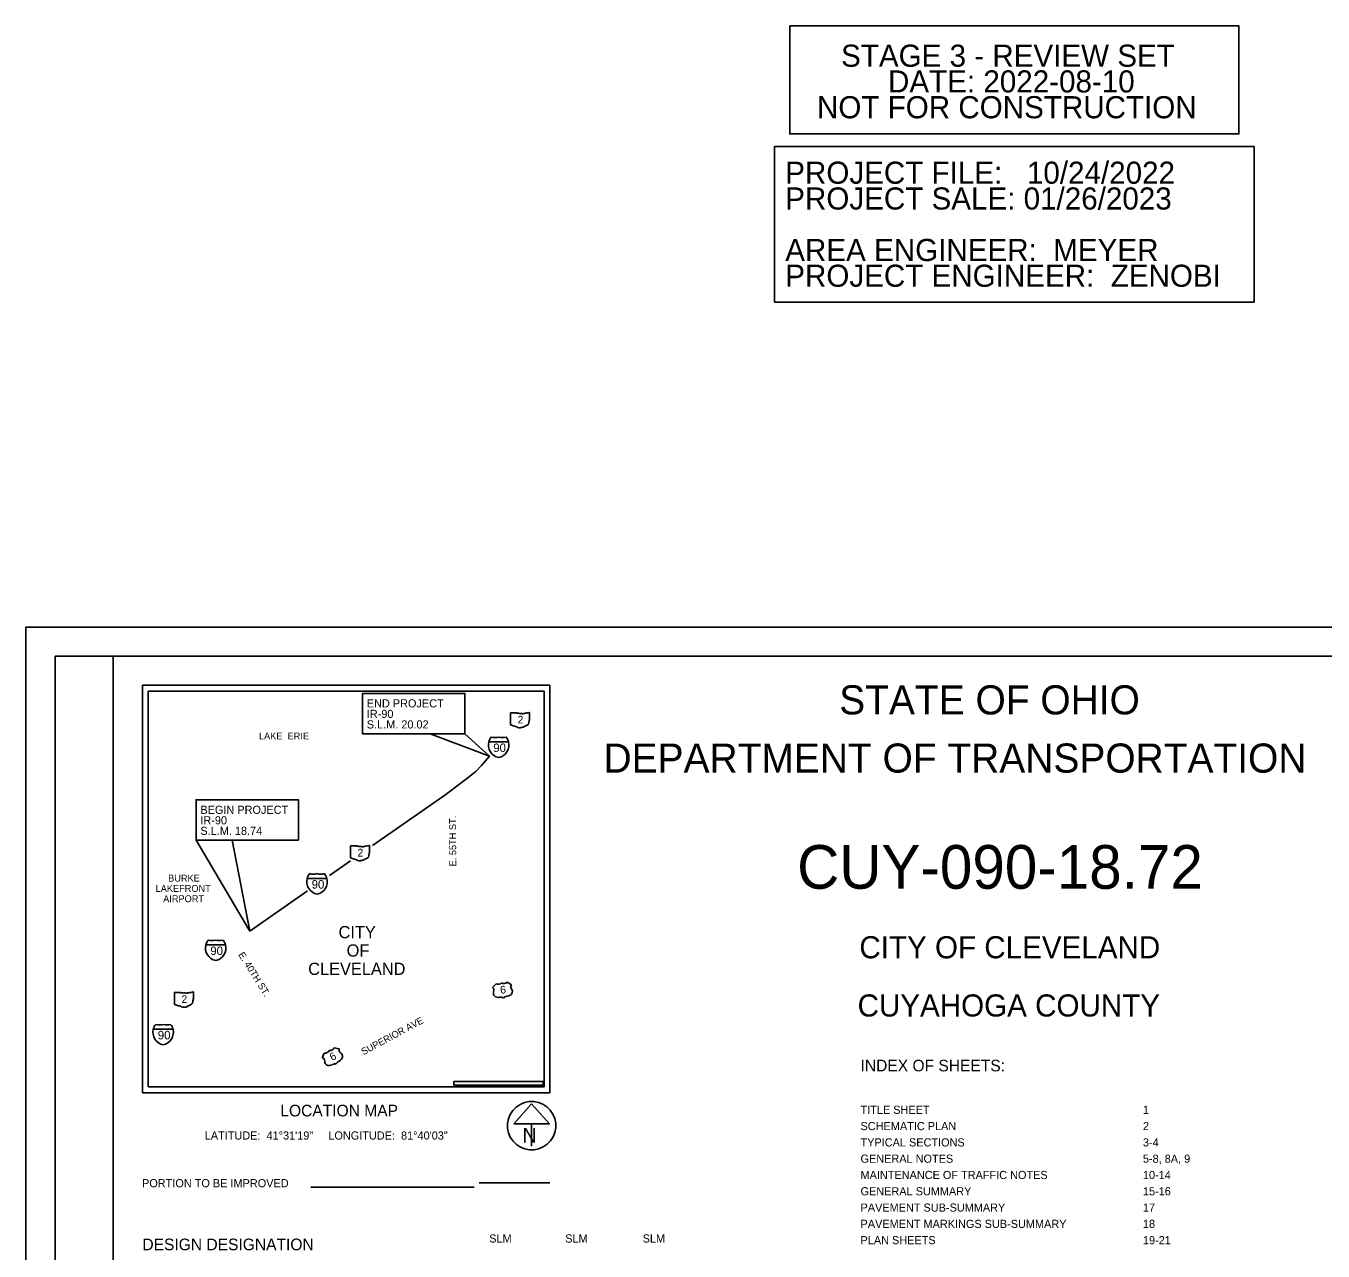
# Model space of a CAD drawing. Extents: x -17.5 to 72.9, y -57.8 to 32.3.
# Drawn here: x 0 to 22.28, y 11.28 to 32.33 of the extents above; entities that cross this region are included whole.
import ezdxf

# ---------------------------------------------------------------- set-up
doc = ezdxf.new("R2010")
doc.units = 0
for name, color, linetype in [('GM_X_Interstate_Shield', 7, 'Continuous'), ('SH_Border', 7, 'Continuous'), ('SH_Cut_Line', 7, 'Continuous'), ('SH_Data', 7, 'Continuous'), ('SH_Text', 7, 'Continuous')]:
    doc.layers.add(name, color=color, linetype=linetype)

msp = doc.modelspace()

# ---------------------------------------------------------------- linework, layer by layer
at = {"layer": 'GM_X_Interstate_Shield'}
for p, q in [((7.949, 20.03), (8.288, 20.03)), ((8.288, 20.03), (7.949, 20.03)), ((8.288, 20.03), (7.949, 20.03)), ((4.831, 17.682), (5.169, 17.682)), ((5.169, 17.682), (4.831, 17.682)), ((5.169, 17.682), (4.831, 17.682)), ((3.09, 16.541), (3.428, 16.541)), ((3.428, 16.541), (3.09, 16.541)), ((3.428, 16.541), (3.09, 16.541)), ((2.188, 15.092), (2.526, 15.092)), ((2.526, 15.092), (2.188, 15.092)), ((2.526, 15.092), (2.188, 15.092))]:
    msp.add_line(p, q, dxfattribs=at)
for centre, start, end in [((8.163, 19.976), 141.669, 165.8066), ((8.054, 20.322), 253.0091, 286.9909), ((8.183, 20.322), 253.0091, 286.9909), ((8.075, 19.976), 14.1934, 38.331), ((8.163, 19.976), 165.8066, 258.463), ((8.075, 19.976), 281.537, 14.1934), ((5.044, 17.628), 165.8066, 258.463), ((5.044, 17.628), 141.669, 165.8066), ((4.936, 17.975), 253.0091, 286.9909), ((5.064, 17.975), 253.0091, 286.9909), ((4.956, 17.628), 281.537, 14.1934), ((4.956, 17.628), 14.1934, 38.331), ((3.303, 16.487), 165.8066, 258.463), ((3.303, 16.487), 141.669, 165.8066), ((3.195, 16.834), 253.0091, 286.9909), ((3.323, 16.834), 253.0091, 286.9909), ((3.215, 16.487), 281.537, 14.1934), ((3.215, 16.487), 14.1934, 38.331), ((2.401, 15.039), 141.669, 165.8066), ((2.293, 15.385), 253.0091, 286.9909), ((2.422, 15.385), 253.0091, 286.9909), ((2.313, 15.039), 14.1934, 38.331), ((2.401, 15.039), 165.8066, 258.463), ((2.313, 15.039), 281.537, 14.1934)]:
    msp.add_arc(centre, 0.22, start, end, dxfattribs=at)
at = {"layer": 'SH_Border'}
for points in [[(0.5, 21.5), (1.5, 21.5), (1.5, 0.5), (0.5, 0.5)], [(1.5, 21.5), (33.5, 21.5), (33.5, 0.5), (1.5, 0.5)]]:
    msp.add_lwpolyline(points, close=True, dxfattribs=at)
at = {"layer": 'SH_Cut_Line'}
msp.add_lwpolyline([(0, 0), (34, 0), (34, 22), (0, 22)], close=True, dxfattribs=at)
at = {"layer": 'SH_Data'}
for p, q in [((2, 21), (9, 21)), ((2, 21), (2, 14)), ((9, 21), (9, 14)), ((2.1, 20.9), (2.1, 14.1)), ((2.1, 20.9), (8.9, 20.9)), ((8.9, 20.9), (8.9, 14.1)), ((8.322, 20.522), (8.322, 20.322)), ((8.322, 20.322), (8.322, 20.522)), ((8.421, 20.525), (8.325, 20.525)), ((8.325, 20.525), (8.421, 20.525)), ((8.651, 20.426), (8.651, 20.53)), ((8.651, 20.53), (8.651, 20.426)), ((8.651, 20.426), (8.651, 20.426)), ((8.651, 20.426), (8.651, 20.426)), ((8.288, 20.03), (7.949, 20.03)), ((8.288, 20.03), (7.949, 20.03)), ((7.826, 19.625), (7.725, 19.522)), ((7.96, 19.785), (7.826, 19.625)), ((7.725, 19.522), (7.546, 19.378)), ((7.333, 19.213), (7.21, 19.122)), ((7.546, 19.378), (7.333, 19.213)), ((5.952, 18.248), (7.21, 19.122)), ((5.573, 18.237), (5.573, 18.037)), ((5.573, 18.037), (5.573, 18.237)), ((5.673, 18.24), (5.576, 18.24)), ((5.576, 18.24), (5.673, 18.24)), ((5.902, 18.141), (5.902, 18.245)), ((5.902, 18.245), (5.902, 18.141)), ((5.902, 18.141), (5.902, 18.141)), ((5.902, 18.141), (5.902, 18.141)), ((5.213, 17.731), (5.573, 17.983)), ((5.169, 17.682), (4.831, 17.682)), ((5.169, 17.682), (4.831, 17.682)), ((3.847, 16.778), (4.835, 17.472)), ((3.428, 16.541), (3.09, 16.541)), ((3.428, 16.541), (3.09, 16.541)), ((8.074, 15.874), (8.014, 15.81)), ((8.014, 15.81), (8.074, 15.874)), ((8.338, 15.856), (8.263, 15.9)), ((8.263, 15.9), (8.338, 15.856)), ((2.549, 15.721), (2.549, 15.52)), ((2.549, 15.52), (2.549, 15.721)), ((2.649, 15.724), (2.553, 15.724)), ((2.553, 15.724), (2.649, 15.724)), ((2.879, 15.624), (2.879, 15.729)), ((2.879, 15.729), (2.879, 15.624)), ((2.879, 15.624), (2.879, 15.624)), ((2.879, 15.624), (2.879, 15.624)), ((8.135, 15.64), (8.148, 15.642)), ((8.148, 15.642), (8.135, 15.64)), ((8.256, 15.657), (8.27, 15.659)), ((8.27, 15.659), (8.256, 15.657)), ((2.526, 15.092), (2.188, 15.092)), ((2.526, 15.092), (2.188, 15.092)), ((5.379, 14.754), (5.294, 14.771)), ((5.294, 14.771), (5.379, 14.754)), ((5.124, 14.683), (5.089, 14.603)), ((5.089, 14.603), (5.124, 14.683)), ((5.26, 14.482), (5.272, 14.489)), ((5.272, 14.489), (5.26, 14.482)), ((5.369, 14.539), (5.381, 14.546)), ((5.381, 14.546), (5.369, 14.539)), ((2.1, 14.1), (8.9, 14.1)), ((2, 14), (9, 14)), ((8.685, 13.809), (8.377, 13.468)), ((8.992, 13.468), (8.685, 13.809)), ((8.377, 13.468), (8.992, 13.468)), ((8.685, 13.468), (8.685, 13.081)), ((8.685, 13.435), (8.685, 13.435)), ((8.685, 13.435), (8.685, 13.435)), ((7.7, 12.377), (4.894, 12.377)), ((7.783, 12.455), (9, 12.455))]:
    msp.add_line(p, q, dxfattribs=at)
for points in [[(5.782, 20.169), (7.539, 20.169), (7.539, 20.862), (5.782, 20.862)], [(5.782, 20.169), (7.539, 20.169), (7.539, 20.862), (5.782, 20.862)], [(6.945, 20.169), (7.96, 19.785), (7.539, 20.169)], [(2.923, 18.341), (4.681, 18.341), (4.681, 19.034), (2.923, 19.034)], [(2.923, 18.341), (4.681, 18.341), (4.681, 19.034), (2.923, 19.034)], [(2.923, 18.341), (3.847, 16.778), (3.54, 18.341)], [(7.35, 14.193), (8.883, 14.193), (8.883, 14.132), (7.35, 14.132)]]:
    msp.add_lwpolyline(points, close=True, dxfattribs=at)
for centre, radius, start, end in [((8.163, 19.976), 0.22, 141.669, 165.8066), ((8.054, 20.322), 0.22, 253.0091, 286.9909), ((8.183, 20.322), 0.22, 253.0091, 286.9909), ((8.075, 19.976), 0.22, 14.1934, 38.331), ((8.163, 19.976), 0.22, 165.8066, 258.463), ((8.075, 19.976), 0.22, 281.537, 14.1934), ((5.044, 17.628), 0.22, 165.8066, 258.463), ((5.044, 17.628), 0.22, 141.669, 165.8066), ((4.936, 17.975), 0.22, 253.0091, 286.9909), ((5.064, 17.975), 0.22, 253.0091, 286.9909), ((4.956, 17.628), 0.22, 281.537, 14.1934), ((4.956, 17.628), 0.22, 14.1934, 38.331), ((3.303, 16.487), 0.22, 165.8066, 258.463), ((3.303, 16.487), 0.22, 141.669, 165.8066), ((3.195, 16.834), 0.22, 253.0091, 286.9909), ((3.323, 16.834), 0.22, 253.0091, 286.9909), ((3.215, 16.487), 0.22, 281.537, 14.1934), ((3.215, 16.487), 0.22, 14.1934, 38.331), ((2.401, 15.039), 0.22, 141.669, 165.8066), ((2.293, 15.385), 0.22, 253.0091, 286.9909), ((2.422, 15.385), 0.22, 253.0091, 286.9909), ((2.313, 15.039), 0.22, 14.1934, 38.331), ((2.401, 15.039), 0.22, 165.8066, 258.463), ((2.313, 15.039), 0.22, 281.537, 14.1934), ((8.685, 13.435), 0.415, 129.7798, 129.7633)]:
    msp.add_arc(centre, radius, start, end, dxfattribs=at)
for centre, major_axis, start_param, end_param in [((8.325, 20.522), (0.00382, 0), 1.712693, 3.28349), ((8.325, 20.522), (0.00382, 0), 1.712693, 3.28349), ((8.444, 20.549), (0.037, 0), 4.042523, 4.731795), ((8.444, 20.549), (0.037, 0), 4.042523, 4.731795), ((8.457, 20.413), (0.133, 0), 1.404758, 1.657858), ((8.457, 20.413), (0.133, 0), 1.404758, 1.657858), ((8.487, 20.523), (0.0107, 0), 3.836095, 5.185415), ((8.487, 20.523), (0.0107, 0), 3.836095, 5.185415), ((8.502, 20.5), (0.0222, 0), 0.950623, 2.079405), ((8.502, 20.5), (0.0222, 0), 0.950623, 2.079405), ((8.531, 20.532), (0.0267, 0), 4.081561, 5.145723), ((8.531, 20.532), (0.0267, 0), 4.081561, 5.145723), ((8.578, 20.464), (0.0703, 0), 1.699011, 2.107814), ((8.578, 20.464), (0.0703, 0), 1.699011, 2.107814), ((8.534, 20.798), (0.35, 0), 4.814394, 5.042369), ((8.534, 20.798), (0.35, 0), 4.814394, 5.042369), ((8.647, 20.531), (0.00367, 0), 6.141152, 7.989035), ((8.647, 20.531), (0.00367, 0), 6.141152, 7.989035), ((8.325, 20.321), (0.00385, 0), 3.00124, 4.508301), ((8.325, 20.321), (0.00385, 0), 3.00124, 4.508301), ((8.326, 20.342), (0.0294, 0), 4.665946, 4.897461), ((8.326, 20.342), (0.0294, 0), 4.665946, 4.897461), ((8.332, 20.31), (0.0106, 0), 0.519207, 1.627899), ((8.332, 20.31), (0.0106, 0), 0.519207, 1.627899), ((8.466, 20.49), (0.252, 0), 4.195997, 4.488961), ((8.466, 20.49), (0.252, 0), 4.195997, 4.488961), ((8.391, 20.232), (0.079, 0), 0.823519, 1.323587), ((8.391, 20.232), (0.079, 0), 0.823519, 1.323587), ((8.476, 20.309), (0.0501, 0), 4.026481, 4.996735), ((8.476, 20.309), (0.0501, 0), 4.026481, 4.996735), ((8.505, 20.24), (0.0412, 0), 1.495662, 1.94098), ((8.505, 20.24), (0.0412, 0), 1.495662, 1.94098), ((8.509, 20.294), (0.0267, 0), 4.691044, 5.507374), ((8.509, 20.294), (0.0267, 0), 4.691044, 5.507374), ((8.533, 20.275), (0.00752, 0), 1.147584, 2.315152), ((8.533, 20.275), (0.00752, 0), 1.147584, 2.315152), ((8.53, 20.302), (0.0282, 0), 4.937069, 5.64225), ((8.53, 20.302), (0.0282, 0), 4.937069, 5.64225), ((8.59, 20.266), (0.0479, 0), 1.647645, 2.488434), ((8.59, 20.266), (0.0479, 0), 1.647645, 2.488434), ((8.553, 20.368), (0.0874, 0), 5.101752, 6.440018), ((8.553, 20.368), (0.0874, 0), 5.101752, 6.440018), ((8.664, 20.382), (0.0248, 0), 2.387724, 3.262537), ((8.664, 20.382), (0.0248, 0), 2.387724, 3.262537), ((8.65, 20.418), (0.00568, 0), 1.883978, 3.671073), ((8.65, 20.418), (0.00568, 0), 1.883978, 3.671073), ((8.614, 20.405), (0.0341, 0), 5.934695, 6.695948), ((8.614, 20.405), (0.0341, 0), 5.934695, 6.695948), ((8.647, 20.425), (0.00393, 0), 5.05454, 6.418171), ((8.647, 20.425), (0.00393, 0), 5.05454, 6.418171), ((5.577, 18.237), (0.00382, 0), 1.712693, 3.28349), ((5.577, 18.237), (0.00382, 0), 1.712693, 3.28349), ((5.696, 18.263), (0.037, 0), 4.042523, 4.731795), ((5.696, 18.263), (0.037, 0), 4.042523, 4.731795), ((5.708, 18.128), (0.133, 0), 1.404758, 1.657858), ((5.708, 18.128), (0.133, 0), 1.404758, 1.657858), ((5.738, 18.238), (0.0107, 0), 3.836095, 5.185415), ((5.738, 18.238), (0.0107, 0), 3.836095, 5.185415), ((5.754, 18.215), (0.0222, 0), 0.950623, 2.079405), ((5.754, 18.215), (0.0222, 0), 0.950623, 2.079405), ((5.782, 18.247), (0.0267, 0), 4.081561, 5.145723), ((5.782, 18.247), (0.0267, 0), 4.081561, 5.145723), ((5.83, 18.179), (0.0703, 0), 1.699011, 2.107814), ((5.83, 18.179), (0.0703, 0), 1.699011, 2.107814), ((5.785, 18.513), (0.35, 0), 4.814394, 5.042369), ((5.785, 18.513), (0.35, 0), 4.814394, 5.042369), ((5.805, 18.083), (0.0874, 0), 5.101752, 6.440018), ((5.805, 18.083), (0.0874, 0), 5.101752, 6.440018), ((5.916, 18.097), (0.0248, 0), 2.387724, 3.262537), ((5.916, 18.097), (0.0248, 0), 2.387724, 3.262537), ((5.902, 18.133), (0.00568, 0), 1.883978, 3.671073), ((5.902, 18.133), (0.00568, 0), 1.883978, 3.671073), ((5.866, 18.12), (0.0341, 0), 5.934695, 6.695948), ((5.866, 18.12), (0.0341, 0), 5.934695, 6.695948), ((5.899, 18.246), (0.00367, 0), 6.141152, 7.989035), ((5.899, 18.246), (0.00367, 0), 6.141152, 7.989035), ((5.899, 18.14), (0.00393, 0), 5.05454, 6.418171), ((5.899, 18.14), (0.00393, 0), 5.05454, 6.418171), ((5.577, 18.036), (0.00385, 0), 3.00124, 4.508301), ((5.577, 18.036), (0.00385, 0), 3.00124, 4.508301), ((5.577, 18.057), (0.0294, 0), 4.665946, 4.897461), ((5.577, 18.057), (0.0294, 0), 4.665946, 4.897461), ((5.583, 18.025), (0.0106, 0), 0.519207, 1.627899), ((5.583, 18.025), (0.0106, 0), 0.519207, 1.627899), ((5.717, 18.205), (0.252, 0), 4.195997, 4.488961), ((5.717, 18.205), (0.252, 0), 4.195997, 4.488961), ((5.642, 17.947), (0.079, 0), 0.823519, 1.323587), ((5.642, 17.947), (0.079, 0), 0.823519, 1.323587), ((5.727, 18.024), (0.0501, 0), 4.026481, 4.996735), ((5.727, 18.024), (0.0501, 0), 4.026481, 4.996735), ((5.756, 17.955), (0.0412, 0), 1.495662, 1.94098), ((5.756, 17.955), (0.0412, 0), 1.495662, 1.94098), ((5.76, 18.009), (0.0267, 0), 4.691044, 5.507374), ((5.76, 18.009), (0.0267, 0), 4.691044, 5.507374), ((5.784, 17.99), (0.00752, 0), 1.147584, 2.315152), ((5.784, 17.99), (0.00752, 0), 1.147584, 2.315152), ((5.781, 18.017), (0.0282, 0), 4.937069, 5.64225), ((5.781, 18.017), (0.0282, 0), 4.937069, 5.64225), ((5.842, 17.98), (0.0479, 0), 1.647645, 2.488434), ((5.842, 17.98), (0.0479, 0), 1.647645, 2.488434), ((8.116, 15.919), (-0.0676, -0.0095), 0.795399, 2.346194), ((8.116, 15.919), (-0.0676, -0.0095), 0.795399, 2.346194), ((8.21, 15.932), (-0.0676, -0.0095), 0.795399, 2.346194), ((8.21, 15.932), (-0.0676, -0.0095), 0.795399, 2.346194), ((8.422, 15.823), (-0.0946, -0.0134), 5.672304, 6.727422), ((8.422, 15.823), (-0.0946, -0.0134), 5.672304, 6.727422), ((2.553, 15.721), (0.00382, 0), 1.712693, 3.28349), ((2.553, 15.721), (0.00382, 0), 1.712693, 3.28349), ((2.672, 15.747), (0.037, 0), 4.042523, 4.731795), ((2.672, 15.747), (0.037, 0), 4.042523, 4.731795), ((2.684, 15.612), (0.133, 0), 1.404758, 1.657858), ((2.684, 15.612), (0.133, 0), 1.404758, 1.657858), ((2.715, 15.722), (0.0107, 0), 3.836095, 5.185415), ((2.715, 15.722), (0.0107, 0), 3.836095, 5.185415), ((2.73, 15.699), (0.0222, 0), 0.950623, 2.079405), ((2.73, 15.699), (0.0222, 0), 0.950623, 2.079405), ((2.759, 15.731), (0.0267, 0), 4.081561, 5.145723), ((2.759, 15.731), (0.0267, 0), 4.081561, 5.145723), ((2.806, 15.663), (0.0703, 0), 1.699011, 2.107814), ((2.806, 15.663), (0.0703, 0), 1.699011, 2.107814), ((2.762, 15.997), (0.35, 0), 4.814394, 5.042369), ((2.762, 15.997), (0.35, 0), 4.814394, 5.042369), ((2.878, 15.617), (0.00568, 0), 1.883978, 3.671073), ((2.878, 15.617), (0.00568, 0), 1.883978, 3.671073), ((2.842, 15.603), (0.0341, 0), 5.934695, 6.695948), ((2.842, 15.603), (0.0341, 0), 5.934695, 6.695948), ((2.875, 15.729), (0.00367, 0), 6.141152, 7.989035), ((2.875, 15.729), (0.00367, 0), 6.141152, 7.989035), ((2.875, 15.624), (0.00393, 0), 5.05454, 6.418171), ((2.875, 15.624), (0.00393, 0), 5.05454, 6.418171), ((7.943, 15.756), (0.0946, 0.0134), 5.838949, 6.894067), ((7.943, 15.756), (0.0946, 0.0134), 5.838949, 6.894067), ((8.123, 15.715), (0.0946, 0.0134), 2.702327, 4.723529), ((8.123, 15.715), (0.0946, 0.0134), 2.702327, 4.723529), ((8.156, 15.587), (-0.0676, -0.0095), 3.785094, 4.712389), ((8.156, 15.587), (-0.0676, -0.0095), 3.785094, 4.712389), ((8.264, 15.603), (-0.0676, -0.0095), 4.712389, 5.639684), ((8.264, 15.603), (-0.0676, -0.0095), 4.712389, 5.639684), ((8.26, 15.735), (-0.0946, -0.0134), 1.559657, 3.580859), ((8.26, 15.735), (-0.0946, -0.0134), 1.559657, 3.580859), ((2.553, 15.52), (0.00385, 0), 3.00124, 4.508301), ((2.553, 15.52), (0.00385, 0), 3.00124, 4.508301), ((2.554, 15.541), (0.0294, 0), 4.665946, 4.897461), ((2.554, 15.541), (0.0294, 0), 4.665946, 4.897461), ((2.56, 15.509), (0.0106, 0), 0.519207, 1.627899), ((2.56, 15.509), (0.0106, 0), 0.519207, 1.627899), ((2.694, 15.689), (0.252, 0), 4.195997, 4.488961), ((2.694, 15.689), (0.252, 0), 4.195997, 4.488961), ((2.618, 15.431), (0.079, 0), 0.823519, 1.323587), ((2.618, 15.431), (0.079, 0), 0.823519, 1.323587), ((2.704, 15.508), (0.0501, 0), 4.026481, 4.996735), ((2.704, 15.508), (0.0501, 0), 4.026481, 4.996735), ((2.733, 15.439), (0.0412, 0), 1.495662, 1.94098), ((2.733, 15.439), (0.0412, 0), 1.495662, 1.94098), ((2.736, 15.493), (0.0267, 0), 4.691044, 5.507374), ((2.736, 15.493), (0.0267, 0), 4.691044, 5.507374), ((2.761, 15.474), (0.00752, 0), 1.147584, 2.315152), ((2.761, 15.474), (0.00752, 0), 1.147584, 2.315152), ((2.757, 15.501), (0.0282, 0), 4.937069, 5.64225), ((2.757, 15.501), (0.0282, 0), 4.937069, 5.64225), ((2.818, 15.464), (0.0479, 0), 1.647645, 2.488434), ((2.818, 15.464), (0.0479, 0), 1.647645, 2.488434), ((2.781, 15.567), (0.0874, 0), 5.101752, 6.440018), ((2.781, 15.567), (0.0874, 0), 5.101752, 6.440018), ((2.892, 15.581), (0.0248, 0), 2.387724, 3.262537), ((2.892, 15.581), (0.0248, 0), 2.387724, 3.262537), ((5.149, 14.739), (-0.0605, -0.0316), 0.795399, 2.346194), ((5.149, 14.739), (-0.0605, -0.0316), 0.795399, 2.346194), ((5.233, 14.784), (-0.0605, -0.0316), 0.795399, 2.346194), ((5.233, 14.784), (-0.0605, -0.0316), 0.795399, 2.346194), ((5.469, 14.752), (-0.0847, -0.0442), 5.672304, 6.727422), ((5.469, 14.752), (-0.0847, -0.0442), 5.672304, 6.727422), ((5.04, 14.528), (0.0847, 0.0442), 5.838949, 6.894067), ((5.04, 14.528), (0.0847, 0.0442), 5.838949, 6.894067), ((5.223, 14.55), (0.0847, 0.0442), 2.702327, 4.723529), ((5.223, 14.55), (0.0847, 0.0442), 2.702327, 4.723529), ((5.297, 14.44), (-0.0605, -0.0316), 3.785094, 4.712389), ((5.297, 14.44), (-0.0605, -0.0316), 3.785094, 4.712389), ((5.394, 14.491), (-0.0605, -0.0316), 4.712389, 5.639684), ((5.394, 14.491), (-0.0605, -0.0316), 4.712389, 5.639684), ((5.346, 14.614), (-0.0847, -0.0442), 1.559657, 3.580859), ((5.346, 14.614), (-0.0847, -0.0442), 1.559657, 3.580859)]:
    msp.add_ellipse(centre, major_axis=major_axis, ratio=0.8, start_param=start_param, end_param=end_param, dxfattribs=at)
at = {"layer": 'SH_Text'}
for points in [[(13.118, 32.327), (20.832, 32.327), (20.832, 30.473), (13.118, 30.473)], [(12.858, 30.254), (21.093, 30.254), (21.093, 27.582), (12.858, 27.582)]]:
    msp.add_lwpolyline(points, close=True, dxfattribs=at)

# ---------------------------------------------------------------- texts
at = {"layer": 'GM_X_Interstate_Shield'}
for p in [(8.026, 19.854), (4.907, 17.507), (3.166, 16.366), (2.265, 14.917)]:
    msp.add_text('90', height=0.1465, dxfattribs=at).set_placement(p)
at = {"layer": 'SH_Data'}
for s, height, p in [('END PROJECT', 0.14, (5.854, 20.62)), ('IR-90', 0.14, (5.854, 20.439)), ('S.L.M. 20.02', 0.14, (5.854, 20.258)), ('2', 0.132, (8.443, 20.344)), ('LAKE  ERIE', 0.1181, (4.002, 20.07)), ('BEGIN PROJECT', 0.14, (2.996, 18.792)), ('IR-90', 0.14, (2.996, 18.611)), ('S.L.M. 18.74', 0.14, (2.996, 18.43)), ('2', 0.132, (5.695, 18.059)), ('BURKE', 0.1181, (2.442, 17.628)), ('LAKEFRONT', 0.1181, (2.227, 17.451)), ('AIRPORT', 0.1181, (2.357, 17.274)), ('CITY', 0.21, (5.369, 16.655)), ('OF', 0.21, (5.508, 16.34)), ('CLEVELAND', 0.21, (4.848, 16.025)), ('2', 0.132, (2.671, 15.543)), ('INDEX OF SHEETS:', 0.2, (14.334, 14.368)), ('TITLE SHEET', 0.14, (14.334, 13.638)), ('1', 0.14, (19.184, 13.638)), ('N', 0.25, (8.529, 13.144)), ('SCHEMATIC PLAN', 0.14, (14.334, 13.358)), ('2', 0.14, (19.184, 13.358)), ('TYPICAL SECTIONS', 0.14, (14.334, 13.078)), ('3-4', 0.14, (19.184, 13.078)), ('GENERAL NOTES', 0.14, (14.334, 12.798)), ('5-8, 8A, 9', 0.14, (19.184, 12.798)), ('MAINTENANCE OF TRAFFIC NOTES', 0.14, (14.334, 12.518)), ('10-14', 0.14, (19.184, 12.518)), ('GENERAL SUMMARY', 0.14, (14.334, 12.238)), ('15-16', 0.14, (19.184, 12.238)), ('PAVEMENT SUB-SUMMARY', 0.14, (14.334, 11.958)), ('17', 0.14, (19.184, 11.958)), ('PAVEMENT MARKINGS SUB-SUMMARY', 0.14, (14.334, 11.678)), ('18', 0.14, (19.184, 11.678)), ('DESIGN DESIGNATION', 0.2, (2, 11.295)), ('SLM', 0.14, (7.957, 11.427)), ('SLM', 0.14, (9.262, 11.427)), ('SLM', 0.14, (10.592, 11.427)), ('PLAN SHEETS', 0.14, (14.334, 11.398)), ('19-21', 0.14, (19.184, 11.398))]:
    msp.add_text(s, height=height, dxfattribs=at).set_placement(p)
for s, height, rotation, p in [('E. 55TH ST.', 0.11812, 90.366, (7.391, 17.89)), ('E. 40TH ST.', 0.11813, 302.1446, (3.641, 16.373)), ('6', 0.132, 8.0353, (8.154, 15.698)), ('SUPERIOR AVE', 0.11812, 28.3, (5.797, 14.644)), ('6', 0.132, 27.5955, (5.259, 14.544))]:
    msp.add_text(s, height=height, rotation=rotation, dxfattribs=at).set_placement(p)
at = {"layer": 'SH_Text'}
for s, height, p in [('STAGE 3 - REVIEW SET', 0.38, (14, 31.626)), ('DATE: 2022-08-10', 0.38, (14.806, 31.184)), ('NOT FOR CONSTRUCTION', 0.38, (13.586, 30.741)), ('PROJECT FILE:   10/24/2022', 0.38, (13.041, 29.616)), ('PROJECT SALE: 01/26/2023', 0.38, (13.041, 29.173)), ('AREA ENGINEER:  MEYER', 0.38, (13.041, 28.288)), ('PROJECT ENGINEER:  ZENOBI', 0.38, (13.041, 27.846)), ('STATE OF OHIO', 0.5, (13.968, 20.5)), ('DEPARTMENT OF TRANSPORTATION', 0.5, (9.92, 19.5)), ('CUY-090-18.72', 0.75, (13.245, 17.505)), ('CITY OF CLEVELAND', 0.38, (14.314, 16.31)), ('CUYAHOGA COUNTY', 0.38, (14.283, 15.31)), ('LOCATION MAP', 0.2, (4.369, 13.594)), ('LATITUDE:  41°31\'19"     LONGITUDE:  81°40\'03"', 0.14, (3.071, 13.196)), ('PORTION TO BE IMPROVED', 0.14, (1.994, 12.377))]:
    msp.add_text(s, height=height, dxfattribs=at).set_placement(p)

doc.saveas('drawing.dxf')
